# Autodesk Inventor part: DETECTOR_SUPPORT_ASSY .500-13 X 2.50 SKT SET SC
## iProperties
Shininess: 64.0
Length Units: 11272
Angle Units: 11279
Time Units: 11290
Mass Units: 11286
Length Display Precision: 3
Angle Display Precision: 2
Compacted: True
Part Number: DETECTOR_SUPPORT_ASSY .500-13 X 2.50 SKT SET SC
Document SubType Name: Modeling
Created: 2004-08
Designer: John Blackburn
Material: STAINLESS_STEEL, AUSTENITIC
Manufacturer: Standard
Standards Organization: Custom
Density: 0.0
Volumn: 0.0
Area: 0.0
PropertySet Name: Model Information
Control State: 0
Master: False
Checked Out: False
Author: John Blackburn
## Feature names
1. Base1
